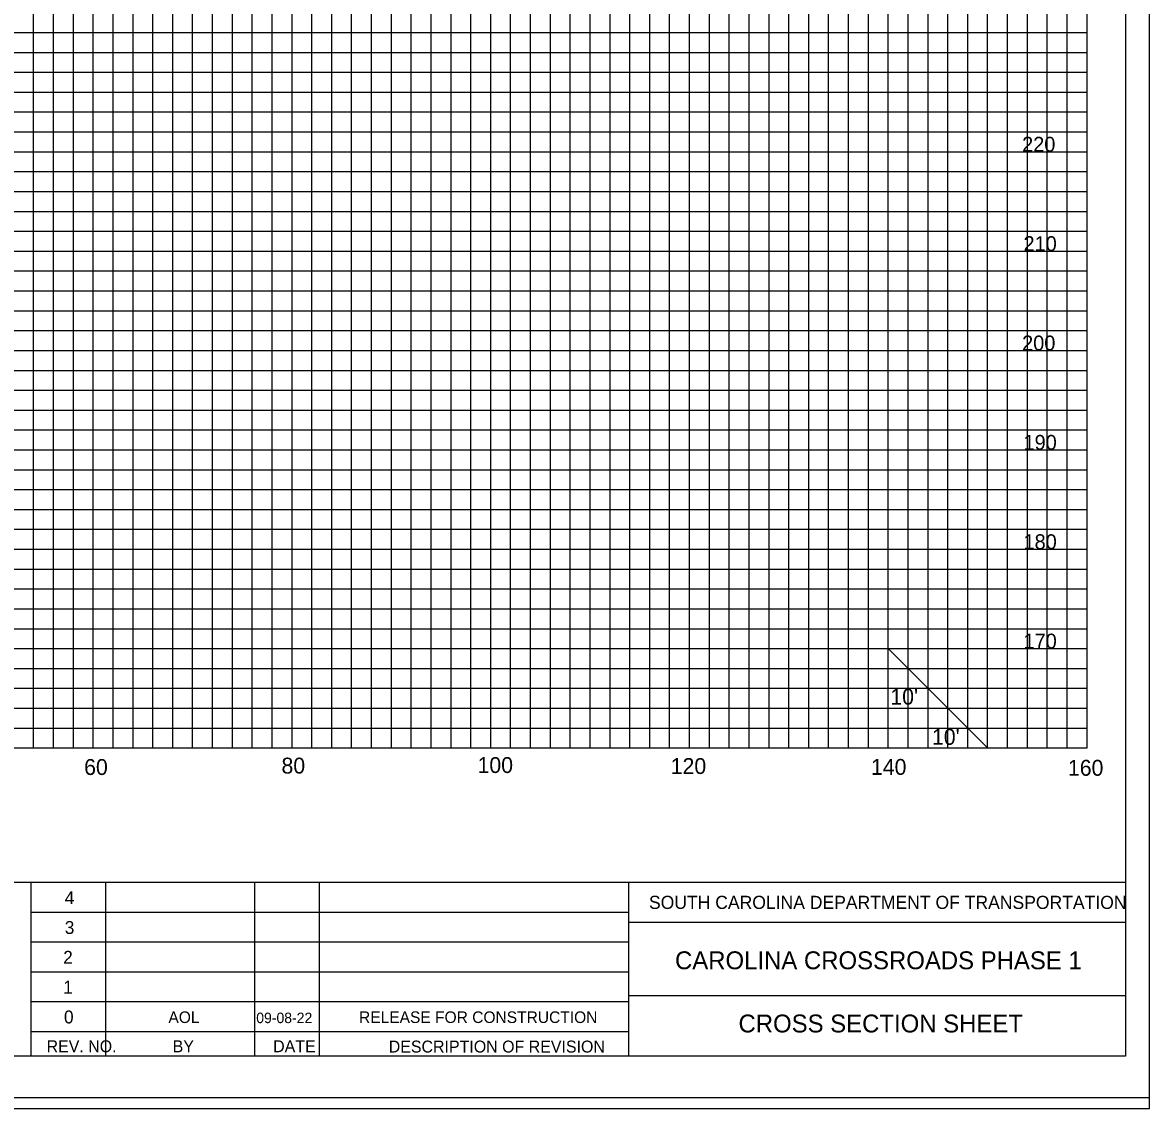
# Model space of a CAD drawing. Extents: x 967 to 1326, y 964 to 3144.
# Drawn here: x 1212.9 to 1326.3, y 1803.7 to 1913 of the extents above; entities that cross this region are included whole.
import ezdxf

# ---------------------------------------------------------------- set-up
doc = ezdxf.new("R2010")
doc.units = 0
for name, color, linetype in [('Default', 7, 'Continuous'), ('RD_GPK_XS_Cell', 7, 'Continuous'), ('RD_XS_ExGround', 7, 'Continuous'), ('RD_XS_ExPaveRet', 7, 'Continuous'), ('RD_XS_Misc_Line', 7, 'Continuous'), ('RD_XS_TX_Elev_EX', 7, 'Continuous'), ('RD_XS_TX_Elev_PR', 7, 'Continuous'), ('RD_XS_TX_Station', 7, 'Continuous')]:
    doc.layers.add(name, color=color, linetype=linetype)

msp = doc.modelspace()

# ---------------------------------------------------------------- linework, layer by layer
at = {"layer": 'RD_GPK_XS_Cell'}
for p, q in [((1220, 1840), (1220, 2010)), ((1230, 1840), (1230, 2010)), ((1240, 1840), (1240, 2010)), ((1250, 1840), (1250, 2010)), ((1260, 1840), (1260, 2010)), ((1270, 1840), (1270, 2010)), ((1280, 1840), (1280, 2010)), ((1290, 1840), (1290, 2010)), ((1300, 1840), (1300, 2010)), ((1310, 1840), (1310, 2010)), ((1320, 1840), (1320, 2010)), ((1000, 1910), (1320, 1910)), ((1000, 1900), (1320, 1900)), ((1000, 1890), (1320, 1890)), ((1000, 1880), (1320, 1880)), ((1000, 1870), (1320, 1870)), ((1000, 1860), (1320, 1860)), ((1000, 1850), (1320, 1850)), ((1000, 1840), (1320, 1840))]:
    msp.add_line(p, q, dxfattribs=at)
at = {"layer": 'RD_XS_ExGround'}
for p, q in [((1214, 1840), (1214, 2010)), ((1216, 1840), (1216, 2010)), ((1218, 1840), (1218, 2010)), ((1222, 1840), (1222, 2010)), ((1224, 1840), (1224, 2010)), ((1226, 1840), (1226, 2010)), ((1228, 1840), (1228, 2010)), ((1232, 1840), (1232, 2010)), ((1234, 1840), (1234, 2010)), ((1236, 1840), (1236, 2010)), ((1238, 1840), (1238, 2010)), ((1242, 1840), (1242, 2010)), ((1244, 1840), (1244, 2010)), ((1246, 1840), (1246, 2010)), ((1248, 1840), (1248, 2010)), ((1252, 1840), (1252, 2010)), ((1254, 1840), (1254, 2010)), ((1256, 1840), (1256, 2010)), ((1258, 1840), (1258, 2010)), ((1262, 1840), (1262, 2010)), ((1264, 1840), (1264, 2010)), ((1266, 1840), (1266, 2010)), ((1268, 1840), (1268, 2010)), ((1272, 1840), (1272, 2010)), ((1274, 1840), (1274, 2010)), ((1276, 1840), (1276, 2010)), ((1278, 1840), (1278, 2010)), ((1282, 1840), (1282, 2010)), ((1284, 1840), (1284, 2010)), ((1286, 1840), (1286, 2010)), ((1288, 1840), (1288, 2010)), ((1292, 1840), (1292, 2010)), ((1294, 1840), (1294, 2010)), ((1296, 1840), (1296, 2010)), ((1298, 1840), (1298, 2010)), ((1302, 1840), (1302, 2010)), ((1304, 1840), (1304, 2010)), ((1306, 1840), (1306, 2010)), ((1308, 1840), (1308, 2010)), ((1312, 1840), (1312, 2010)), ((1314, 1840), (1314, 2010)), ((1316, 1840), (1316, 2010)), ((1318, 1840), (1318, 2010)), ((1000, 1912), (1320, 1912)), ((1000, 1908), (1320, 1908)), ((1000, 1906), (1320, 1906)), ((1000, 1904), (1320, 1904)), ((1000, 1902), (1320, 1902)), ((1000, 1898), (1320, 1898)), ((1000, 1896), (1320, 1896)), ((1000, 1894), (1320, 1894)), ((1000, 1892), (1320, 1892)), ((1000, 1888), (1320, 1888)), ((1000, 1886), (1320, 1886)), ((1000, 1884), (1320, 1884)), ((1000, 1882), (1320, 1882)), ((1000, 1878), (1320, 1878)), ((1000, 1876), (1320, 1876)), ((1000, 1874), (1320, 1874)), ((1000, 1872), (1320, 1872)), ((1000, 1868), (1320, 1868)), ((1000, 1866), (1320, 1866)), ((1000, 1864), (1320, 1864)), ((1000, 1862), (1320, 1862)), ((1000, 1858), (1320, 1858)), ((1000, 1856), (1320, 1856)), ((1000, 1854), (1320, 1854)), ((1000, 1852), (1320, 1852)), ((1000, 1848), (1320, 1848)), ((1000, 1846), (1320, 1846)), ((1000, 1844), (1320, 1844)), ((1000, 1842), (1320, 1842))]:
    msp.add_line(p, q, dxfattribs=at)
at = {"layer": 'RD_XS_ExPaveRet'}
for points in [[(967.41, 1803.72), (1326.28, 1803.72), (1326.28, 2023.72), (967.41, 2023.72)], [(988.52, 1804.84), (1326.28, 1804.84), (1326.28, 2022.6), (988.52, 2022.6)]]:
    msp.add_lwpolyline(points, close=True, dxfattribs=at)
at = {"layer": 'RD_XS_Misc_Line'}
msp.add_line((1300, 1850), (1310, 1840), dxfattribs=at)
at = {"layer": 'RD_XS_TX_Elev_EX'}
for p, q in [((1323.89, 2018.46), (1323.89, 1808.98)), ((996.11, 1826.49), (1323.89, 1826.49)), ((1213.76, 1808.94), (1213.76, 1826.49)), ((1221.26, 1808.95), (1221.26, 1826.48)), ((1236.26, 1808.95), (1236.26, 1826.48)), ((1242.76, 1808.95), (1242.76, 1826.48)), ((1273.88, 1808.98), (1273.88, 1826.49)), ((1213.76, 1823.48), (1273.88, 1823.48)), ((1323.93, 1822.43), (1273.88, 1822.43)), ((1213.76, 1820.48), (1273.88, 1820.48)), ((1213.76, 1817.48), (1273.88, 1817.48)), ((1213.76, 1814.48), (1273.88, 1814.48)), ((1323.89, 1815.04), (1273.88, 1815.04)), ((1213.76, 1811.48), (1273.88, 1811.48)), ((1323.89, 1808.98), (996.11, 1808.98))]:
    msp.add_line(p, q, dxfattribs=at)
at = {"layer": 'RD_XS_TX_Station'}
msp.add_lwpolyline([(967.41, 1803.72), (1326.28, 1803.72), (1326.28, 2023.72), (967.41, 2023.72)], close=True, dxfattribs=at)

# ---------------------------------------------------------------- texts
at = {"layer": 'Default'}
for s, p in [('220', (1313.47, 1900)), ('210', (1313.61, 1890)), ('200', (1313.47, 1880)), ('190', (1313.61, 1870)), ('180', (1313.61, 1860)), ('170', (1313.61, 1850))]:
    msp.add_text(s, height=1.5, dxfattribs=at).set_placement(p)
at = {"layer": 'RD_XS_Misc_Line'}
for s, height, p in [("10'", 1.6, (1300.21, 1844.36)), ("10'", 1.6, (1304.4, 1840.32)), ('60', 1.6, (1219.08, 1837.28)), ('80', 1.6, (1238.94, 1837.42)), ('100', 1.6, (1258.67, 1837.48)), ('120', 1.6, (1278.11, 1837.38)), ('140', 1.6, (1298.26, 1837.29)), ('160', 1.6, (1318.08, 1837.2)), ('4', 1.3, (1217.13, 1824.28)), ('SOUTH CAROLINA DEPARTMENT OF TRANSPORTATION', 1.32, (1275.92, 1823.8)), ('3', 1.3, (1217.13, 1821.28)), ('2', 1.3, (1216.97, 1818.28)), ('1', 1.3, (1216.97, 1815.28)), ('0', 1.3, (1217.05, 1812.28)), ('REV. NO.', 1.2, (1215.3, 1809.38)), ('BY', 1.2, (1227.99, 1809.38)), ('DATE', 1.2, (1238.1, 1809.38)), ('DESCRIPTION OF REVISION', 1.2, (1249.73, 1809.35))]:
    msp.add_text(s, height=height, dxfattribs=at).set_placement(p)
for s, p in [('CAROLINA CROSSROADS PHASE 1', (1278.54, 1817.73)), ('CROSS SECTION SHEET', (1284.93, 1811.37))]:
    msp.add_text(s, height=1.8, rotation=0, dxfattribs=at).set_placement(p)
at = {"layer": 'RD_XS_TX_Elev_PR'}
for s, height, p in [('AOL', 1.17, (1227.56, 1812.32)), ('09-08-22', 1.053, (1236.4, 1812.31)), ('RELEASE FOR CONSTRUCTION', 1.17, (1246.74, 1812.32))]:
    msp.add_text(s, height=height, dxfattribs=at).set_placement(p)

doc.saveas('drawing.dxf')
